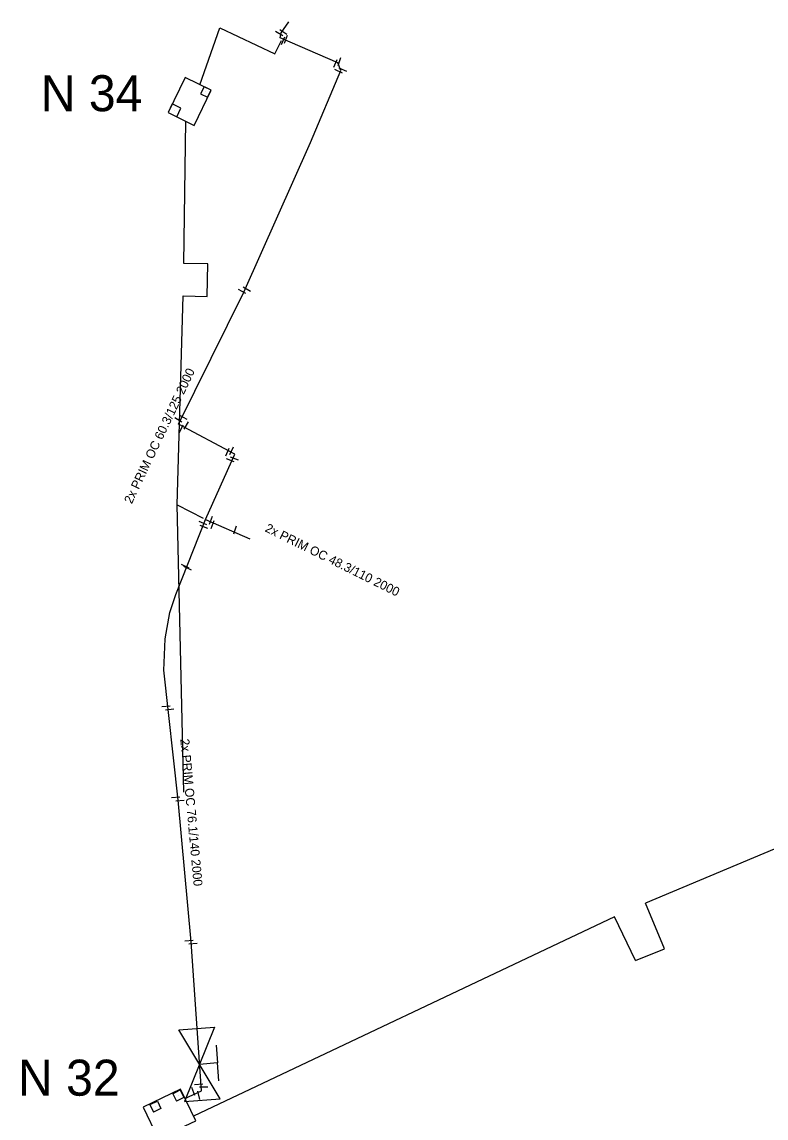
# Model space of a CAD drawing. Extents: x -642943 to -623314, y -1138561 to -1113539.
# Drawn here: x -641998.4 to -641936.4, y -1115287.6 to -1115196.3 of the extents above; entities that cross this region are included whole.
import ezdxf

# ---------------------------------------------------------------- set-up
doc = ezdxf.new("R2010")
doc.units = 0
for name, color, linetype in [('horkovod armatury', 7, 'Continuous'), ('horkovod dimenze', 7, 'Continuous'), ('horkovod předisol', 7, 'Continuous'), ('horkovod sváry', 7, 'Continuous'), ('horkovod trasa', 7, 'Continuous'), ('horkovod zrušený', 7, 'Continuous'), ('horkovod číslo šachty', 7, 'Continuous'), ('horkovod šachty', 7, 'Continuous')]:
    doc.layers.add(name, color=color, linetype=linetype)

# ---------------------------------------------------------------- blocks, each defined once
blk = doc.blocks.new('POINT_DISPLAY')
blk.add_line((0, 0), (0, 0))
blk = doc.blocks.new('SPH')
at = {"layer": 'horkovod sváry'}
blk.add_line((0, -0.035), (0, 0.035), dxfattribs=at)
blk = doc.blocks.new('SCH_01_7')
at = {"layer": 'horkovod armatury'}
for p, q in [((10, 5), (-10, -5)), ((-10, -5), (-10, 5)), ((-10, 5), (10, -5)), ((-5, 5), (0, 5)), ((0, 5), (0, 0)), ((5, 5), (0, 5)), ((10, -5), (10, 5))]:
    blk.add_line(p, q, dxfattribs=at)

msp = doc.modelspace()

# ---------------------------------------------------------------- linework, layer by layer
at = {"layer": 'horkovod předisol'}
for p, q in [((-641983.123, -1115237.725), (-641979.449, -1115239.329)), ((-641984.841, -1115285.972), (-641983.464, -1115285.348))]:
    msp.add_line(p, q, dxfattribs=at)
for points in [[(-641983.123, -1115237.725), (-641980.691, -1115232.282), (-641985.384, -1115229.788), (-641979.922, -1115218.791), (-641974.375, -1115206.318), (-641971.841, -1115200.318), (-641972.086, -1115199.673), (-641976.91, -1115197.596), (-641976.824, -1115197.183), (-641976.174, -1115196.272)], [(-641985.423, -1115261.105), (-641986.598, -1115250.279), (-641986.589, -1115249.676), (-641986.498, -1115247.681), (-641986.1, -1115245.478), (-641985.602, -1115243.982), (-641983.123, -1115237.725)], [(-641983.464, -1115285.348), (-641984.33, -1115272.933), (-641985.423, -1115261.105)]]:
    msp.add_lwpolyline(points, dxfattribs=at)
at = {"layer": 'horkovod trasa'}
for p, q in [((-641983.123, -1115237.725), (-641979.449, -1115239.329)), ((-641909.621, -1115254.229), (-641946.437, -1115269.702)), ((-641944.87, -1115273.491), (-641946.437, -1115269.702)), ((-641949.035, -1115270.824), (-641984.129, -1115287.444)), ((-641947.273, -1115274.485), (-641949.035, -1115270.824)), ((-641947.273, -1115274.485), (-641944.87, -1115273.491)), ((-641984.841, -1115285.972), (-641983.464, -1115285.348))]:
    msp.add_line(p, q, dxfattribs=at)
for points in [[(-641983.123, -1115237.725), (-641980.691, -1115232.282), (-641985.384, -1115229.788), (-641979.922, -1115218.791), (-641974.375, -1115206.318), (-641971.841, -1115200.318), (-641972.086, -1115199.673), (-641976.91, -1115197.596), (-641976.824, -1115197.183), (-641976.174, -1115196.272)], [(-641985.423, -1115261.105), (-641986.598, -1115250.279), (-641986.589, -1115249.676), (-641986.498, -1115247.681), (-641986.1, -1115245.478), (-641985.602, -1115243.982), (-641983.123, -1115237.725)], [(-641983.464, -1115285.348), (-641984.33, -1115272.933), (-641985.423, -1115261.105)]]:
    msp.add_lwpolyline(points, dxfattribs=at)
at = {"layer": 'horkovod zrušený'}
for p, q in [((-641983.25, -1115201.668), (-641983.535, -1115202.251)), ((-641982.665, -1115201.954), (-641983.25, -1115201.668)), ((-641983.535, -1115202.251), (-641982.952, -1115202.537)), ((-641982.952, -1115202.537), (-641982.665, -1115201.954)), ((-641985.897, -1115203.105), (-641986.249, -1115203.823)), ((-641985.179, -1115203.457), (-641985.897, -1115203.105)), ((-641985.531, -1115204.175), (-641985.179, -1115203.457)), ((-641986.249, -1115203.823), (-641985.531, -1115204.175)), ((-641985.502, -1115236.507), (-641983.326, -1115237.61))]:
    msp.add_line(p, q, dxfattribs=at)
for points in [[(-641983.614, -1115201.508), (-641981.939, -1115196.777), (-641977.343, -1115198.938), (-641976.795, -1115197.831)], [(-641985.502, -1115236.507), (-641984.987, -1115219.091), (-641982.988, -1115219.15), (-641982.929, -1115216.432), (-641984.929, -1115216.408), (-641984.784, -1115204.553), (-641984.779, -1115204.539)], [(-641984.928, -1115260.446), (-641985.502, -1115236.507)]]:
    msp.add_lwpolyline(points, dxfattribs=at)
msp.add_lwpolyline([(-641982.67, -1115201.954), (-641984.836, -1115200.908), (-641986.25, -1115203.829), (-641984.071, -1115204.907)], close=True, dxfattribs=at)
at = {"layer": 'horkovod šachty'}
for p, q in [((-641985.867, -1115285.571), (-641985.24, -1115285.258)), ((-641985.867, -1115285.571), (-641985.554, -1115286.198)), ((-641985.24, -1115285.258), (-641984.927, -1115285.885)), ((-641987.77, -1115286.475), (-641987.134, -1115286.183)), ((-641987.77, -1115286.475), (-641987.478, -1115287.111)), ((-641987.134, -1115286.183), (-641986.842, -1115286.819)), ((-641984.927, -1115285.885), (-641985.554, -1115286.198)), ((-641986.842, -1115286.819), (-641987.478, -1115287.111))]:
    msp.add_line(p, q, dxfattribs=at)
msp.add_lwpolyline([(-641983.938, -1115287.841), (-641985.214, -1115285.187), (-641988.323, -1115286.682), (-641987.066, -1115289.296), (-641983.938, -1115287.841)], dxfattribs=at)

# ---------------------------------------------------------------- block references
at = {"layer": 'horkovod armatury', "xscale": 0.2999604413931, "yscale": 0.2999604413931, "rotation": -85.53034691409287}
msp.add_blockref('SCH_01_7', (-641983.63, -1115283.128), dxfattribs=at)
at = {"layer": 'horkovod sváry'}
for p, xscale, yscale, rotation in [((-641976.997, -1115197.24), 10.000005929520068, 10.000005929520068, 59.03624346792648), ((-641976.637, -1115197.13), 10.00000237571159, 10.000002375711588, 56.555459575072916), ((-641976.657, -1115197.83), 9.999984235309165, 9.999984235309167, -21.943354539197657), ((-641976.427, -1115197.71), 9.999991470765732, 9.999991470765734, -21.206271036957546), ((-641972.287, -1115199.73), 10.000001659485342, 10.000001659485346, -23.163066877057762), ((-641971.957, -1115199.57), 9.999994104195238, 9.999994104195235, -20.370368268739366), ((-641972.027, -1115200.39), 10.000021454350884, 10.000021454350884, 65.17786344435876), ((-641971.677, -1115200.26), 10.000014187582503, 10.000014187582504, 65.28685616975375), ((-641980.067, -1115218.74), 10.000020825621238, 10.00002082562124, 62.598854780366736), ((-641979.677, -1115218.55), 9.999997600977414, 9.999997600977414, 60.80698710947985), ((-641984.967, -1115229.22), 10.00001114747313, 10.000011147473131, 61.91632297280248), ((-641985.387, -1115229.44), 9.999988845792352, 9.999988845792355, 57.441737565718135), ((-641985.147, -1115230.16), 9.999992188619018, 9.999992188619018, -26.99865980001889), ((-641984.727, -1115229.91), 9.999981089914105, 9.999981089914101, -29.670653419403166), ((-641981.297, -1115232.11), 9.999991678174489, 9.999991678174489, -24.20377975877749), ((-641980.947, -1115231.99), 9.999970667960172, 9.999970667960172, -24.200908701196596), ((-641981.067, -1115232.8), 10.000012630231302, 10.000012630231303, 68.55863152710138), ((-641980.717, -1115232.66), 10.000007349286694, 10.000007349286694, 67.92460918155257), ((-641983.347, -1115238.03), 10.000028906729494, 10.00002890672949, 67.36730793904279), ((-641983.257, -1115238.35), 10.000000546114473, 10.000000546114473, 68.74938397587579), ((-641982.677, -1115237.79), 10.000011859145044, 10.000011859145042, -21.67660721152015), ((-641982.527, -1115238.15), 9.999998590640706, 9.999998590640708, -20.51557484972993), ((-641980.691, -1115238.621), 10.00000343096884, 10.00000343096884, 161.58369717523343), ((-641984.817, -1115241.64), 10.00001797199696, 10.00001797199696, 64.25338212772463), ((-641984.607, -1115241.8), 9.999977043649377, 9.999977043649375, 65.55608938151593), ((-641986.437, -1115253.29), 9.9999967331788, 9.9999967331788, -84.21170063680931), ((-641986.127, -1115253.55), 9.999983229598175, 9.999983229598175, -83.13496399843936), ((-641985.617, -1115260.86), 9.999988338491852, 9.999988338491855, -85.58668405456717), ((-641985.257, -1115261.14), 9.999987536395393, 9.999987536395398, -84.28945995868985), ((-641984.497, -1115272.81), 9.999994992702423, 9.999994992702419, -84.80566771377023), ((-641984.167, -1115273.05), 9.999977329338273, 9.999977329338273, -84.69018057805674), ((-641983.707, -1115284.78), 10.00000421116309, 10.00000421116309, -87.06813890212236), ((-641984.147, -1115285.4), 9.999981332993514, 9.999981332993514, 19.3443399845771), ((-641983.677, -1115285.71), 10.000007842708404, 10.000007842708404, 14.13744933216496), ((-641983.277, -1115285), 10.000020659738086, 10.000020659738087, -88.1293704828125)]:
    msp.add_blockref('SPH', p, dxfattribs=dict(at, xscale=xscale, yscale=yscale, rotation=rotation))
at = {"layer": 'horkovod zrušený'}
for p in [(-641983.094, -1115202.1), (-641985.714, -1115203.64)]:
    msp.add_blockref('POINT_DISPLAY', p, dxfattribs=at)
at = {"layer": 'horkovod šachty'}
for p in [(-641985.397, -1115285.728), (-641987.306, -1115286.647)]:
    msp.add_blockref('POINT_DISPLAY', p, dxfattribs=at)

# ---------------------------------------------------------------- texts
at = {"layer": 'horkovod dimenze'}
for s, height, rotation, p in [('2x PRIM OC 60.3/125 2000', 0.74999, 64.59466, (-641989.28, -1115236.482)), ('2x PRIM OC 48.3/110 2000', 0.74998, 333.65571, (-641978.229, -1115238.695)), ('2x PRIM OC 76.1/140 2000', 0.74998, 275.22913, (-641985.235, -1115256.036))]:
    msp.add_text(s, height=height, rotation=rotation, dxfattribs=at).set_placement(p)
at = {"layer": 'horkovod číslo šachty'}
for s, p in [('N 34', (-641996.866, -1115203.712)), ('N 32', (-641998.766, -1115285.739))]:
    msp.add_text(s, height=3, dxfattribs=at).set_placement(p)

doc.saveas('drawing.dxf')
